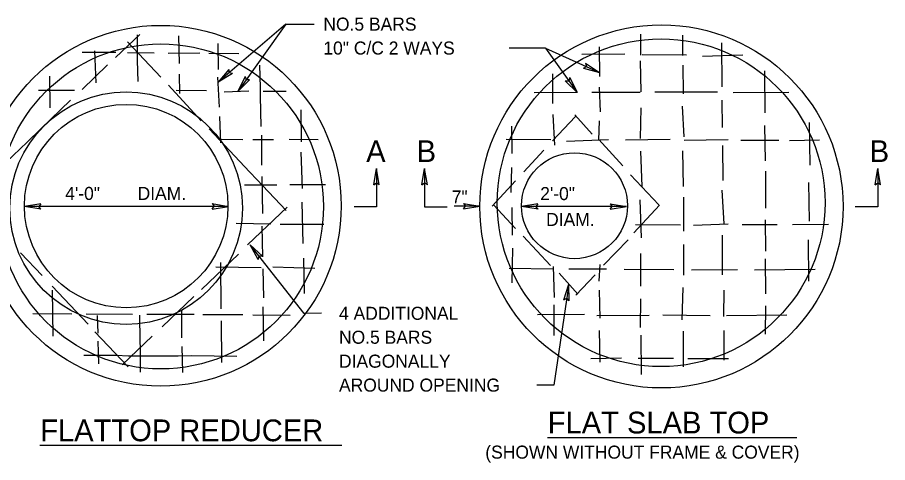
# Model space of a CAD drawing. Extents: x 1.8 to 9.1, y -6 to 4.
# Drawn here: x 5.032 to 9.029, y 1.931 to 3.977 of the extents above; entities that cross this region are included whole.
import ezdxf

# ---------------------------------------------------------------- set-up
doc = ezdxf.new("R2010")
doc.units = 0
for name, color, linetype in [('DETL-DIMS', 7, 'Continuous'), ('DETL-LINE', 7, 'Continuous'), ('DETL-NOTE', 7, 'Continuous'), ('DETL-TITL', 7, 'Continuous')]:
    doc.layers.add(name, color=color, linetype=linetype)

msp = doc.modelspace()

# ---------------------------------------------------------------- linework, layer by layer
at = {"layer": 'DETL-DIMS'}
for p, q in [((6.2643, 3.9457), (5.9535, 3.6792)), ((6.2643, 3.9457), (6.0444, 3.6358)), ((6.2643, 3.9457), (6.3953, 3.9457)), ((7.4577, 3.8358), (7.2901, 3.8358)), ((7.4577, 3.8358), (7.6027, 3.6313)), ((7.4577, 3.8358), (7.7054, 3.7231)), ((7.642, 3.7659), (7.7054, 3.7231)), ((7.642, 3.7659), (7.6454, 3.7505)), ((6.0027, 3.7379), (5.9535, 3.6792)), ((6.0191, 3.7187), (5.9535, 3.6792)), ((6.0027, 3.7379), (6.0037, 3.7222)), ((6.0191, 3.7187), (6.0037, 3.7222)), ((7.6316, 3.743), (7.6454, 3.7505)), ((7.6316, 3.743), (7.7054, 3.7231)), ((6.0779, 3.7046), (6.0444, 3.6358)), ((6.0984, 3.69), (6.0444, 3.6358)), ((6.0779, 3.7046), (6.0827, 3.6896)), ((6.0984, 3.69), (6.0827, 3.6896)), ((7.5488, 3.6856), (7.6027, 3.6313)), ((7.5488, 3.6856), (7.5645, 3.6851)), ((7.5693, 3.7001), (7.5645, 3.6851)), ((7.5693, 3.7001), (7.6027, 3.6313)), ((6.6686, 3.2069), (6.6809, 3.2824)), ((6.6937, 3.207), (6.6809, 3.2824)), ((6.8898, 3.207), (6.9026, 3.2824)), ((6.9149, 3.2069), (6.9026, 3.2824)), ((8.9716, 3.2069), (8.9839, 3.2824)), ((8.9967, 3.207), (8.9839, 3.2824)), ((6.6686, 3.2069), (6.6811, 3.2164)), ((6.6937, 3.207), (6.6811, 3.2164)), ((6.8898, 3.207), (6.9024, 3.2164)), ((6.9149, 3.2069), (6.9024, 3.2164)), ((8.9716, 3.2069), (8.9841, 3.2164)), ((8.9967, 3.207), (8.9841, 3.2164)), ((5.1396, 3.1206), (5.0641, 3.1084)), ((5.1396, 3.1206), (5.1301, 3.1081)), ((5.926, 3.1213), (6.0014, 3.1084)), ((5.926, 3.1213), (5.9354, 3.1086)), ((5.926, 3.1213), (6.0014, 3.1084)), ((5.926, 3.1213), (5.9354, 3.1086)), ((7.0804, 3.1216), (7.156, 3.1095)), ((7.0804, 3.1216), (7.0899, 3.1091)), ((7.4232, 3.1204), (7.3478, 3.1075)), ((7.4232, 3.1204), (7.4138, 3.1077)), ((7.7542, 3.1199), (7.8297, 3.1075)), ((7.7542, 3.1199), (7.7637, 3.1073)), ((5.1395, 3.0955), (5.0641, 3.1084)), ((6.0014, 3.1084), (5.0641, 3.1084)), ((5.1395, 3.0955), (5.1301, 3.1081)), ((5.9259, 3.0961), (5.9354, 3.1086)), ((5.9259, 3.0961), (5.9354, 3.1086)), ((5.9259, 3.0961), (6.0014, 3.1084)), ((5.9259, 3.0961), (6.0014, 3.1084)), ((7.156, 3.1095), (7.0381, 3.1095)), ((7.0806, 3.0964), (7.156, 3.1095)), ((7.0806, 3.0964), (7.0899, 3.1091)), ((7.4233, 3.0952), (7.3478, 3.1075)), ((7.8297, 3.1075), (7.3478, 3.1075)), ((7.4233, 3.0952), (7.4138, 3.1077)), ((7.7543, 3.0947), (7.8297, 3.1075)), ((7.7543, 3.0947), (7.7637, 3.1073)), ((6.3487, 2.6164), (6.1011, 2.9308)), ((6.1379, 2.8637), (6.1011, 2.9308)), ((6.1577, 2.8793), (6.1011, 2.9308)), ((6.1379, 2.8637), (6.142, 2.8789)), ((6.1577, 2.8793), (6.142, 2.8789)), ((7.5653, 2.7513), (7.4962, 2.2869)), ((7.5417, 2.6785), (7.5653, 2.7513)), ((7.5666, 2.6748), (7.5653, 2.7513)), ((7.5417, 2.6785), (7.5556, 2.686)), ((7.5666, 2.6748), (7.5556, 2.686)), ((6.4291, 2.6169), (6.3487, 2.6164)), ((7.4962, 2.2869), (7.4177, 2.2869))]:
    msp.add_line(p, q, dxfattribs=at)
for points in [[(6.6809, 3.2824), (6.6809, 3.1055), (6.578, 3.1055)], [(6.9026, 3.2824), (6.9026, 3.1055), (7.0056, 3.1055)], [(8.9839, 3.2824), (8.9839, 3.1055), (8.8809, 3.1055)]]:
    msp.add_lwpolyline(points, dxfattribs=at)
at = {"layer": 'DETL-LINE'}
for p, q in [((5.5938, 3.8977), (5.4829, 3.7919)), ((5.5835, 3.8021), (5.5834, 3.8972)), ((5.7724, 3.8922), (5.7755, 3.7655)), ((7.896, 3.8028), (7.8955, 3.9001)), ((8.0869, 3.8956), (8.0865, 3.8016)), ((5.6898, 3.7025), (5.5379, 3.8641)), ((5.9551, 3.7378), (5.9545, 3.8564)), ((7.704, 3.8406), (7.7057, 3.7052)), ((8.2701, 3.657), (8.2676, 3.86)), ((5.3286, 3.8172), (5.4838, 3.8168)), ((5.3862, 3.8229), (5.3914, 3.6755)), ((5.5379, 3.8147), (5.6592, 3.8137)), ((5.583, 3.7786), (5.5835, 3.8021)), ((5.7246, 3.8122), (5.8695, 3.8136)), ((5.9118, 3.8115), (6.0487, 3.8104)), ((7.6243, 3.8072), (7.8222, 3.8089)), ((7.9026, 3.8066), (8.1062, 3.8041)), ((8.1786, 3.7988), (8.3638, 3.8047)), ((5.4449, 3.759), (5.3294, 3.6449)), ((5.586, 3.6825), (5.583, 3.7786)), ((7.8965, 3.6349), (7.8943, 3.7774)), ((6.1436, 3.7569), (6.1462, 3.6547)), ((8.0886, 3.7565), (8.0902, 3.6253)), ((8.4639, 3.731), (8.4659, 3.5378)), ((5.1794, 3.7067), (5.1813, 3.5613)), ((5.7745, 3.7162), (5.7763, 3.6276)), ((5.9602, 3.5645), (5.9523, 3.7013)), ((7.4915, 3.5817), (7.4917, 3.7176)), ((5.2945, 3.6402), (5.1284, 3.6405)), ((5.8763, 3.5019), (5.726, 3.6653)), ((5.9005, 3.6393), (5.7603, 3.64)), ((6.1462, 3.6547), (6.1475, 3.6147)), ((7.7041, 3.6554), (7.7089, 3.5426)), ((6.0947, 3.6374), (5.9812, 3.6338)), ((6.1475, 3.6147), (6.1506, 3.4758)), ((6.2669, 3.6355), (6.161, 3.6358)), ((7.6012, 3.6313), (7.4057, 3.6305)), ((7.8932, 3.6316), (7.6699, 3.6322)), ((8.2477, 3.6329), (7.9595, 3.6325)), ((8.5759, 3.632), (8.3196, 3.63)), ((5.2758, 3.5967), (5.139, 3.4646)), ((7.8948, 3.4196), (7.8969, 3.5607)), ((8.0863, 3.5684), (8.0937, 3.4274)), ((8.2711, 3.4713), (8.269, 3.5968)), ((5.9656, 3.4006), (5.9614, 3.5217)), ((6.337, 3.4055), (6.3357, 3.5523)), ((7.4901, 3.4087), (7.5953, 3.5217)), ((7.501, 3.39), (7.4937, 3.53)), ((7.5924, 3.5292), (7.6723, 3.4408)), ((7.7049, 3.5007), (7.7007, 3.4123)), ((8.4643, 3.4795), (8.4666, 3.3168)), ((8.674, 3.2979), (8.6702, 3.4944)), ((5.139, 3.4646), (5.0769, 3.4035)), ((6.0987, 3.2651), (5.9121, 3.4648)), ((7.3012, 3.4771), (7.3037, 3.3506)), ((5.0769, 3.4035), (4.9456, 3.2815)), ((6.0678, 3.4136), (5.9554, 3.416)), ((6.2085, 3.4147), (6.113, 3.4142)), ((6.1524, 3.4352), (6.1527, 3.2978)), ((6.4127, 3.4134), (6.28, 3.4148)), ((7.277, 3.4168), (7.483, 3.4148)), ((7.5545, 3.4086), (7.7467, 3.4154)), ((7.7035, 3.4156), (7.8127, 3.295)), ((7.8253, 3.4135), (8.0307, 3.4172)), ((8.0946, 3.4128), (8.2963, 3.416)), ((8.3556, 3.4121), (8.53, 3.4127)), ((8.5794, 3.4102), (8.7171, 3.4138)), ((7.3587, 3.2673), (7.4508, 3.3671)), ((7.9012, 3.1992), (7.8951, 3.3622)), ((8.0874, 3.3639), (8.0906, 3.1994)), ((8.2734, 3.2273), (8.273, 3.3876)), ((6.341, 3.1898), (6.3352, 3.3576)), ((7.3017, 3.2867), (7.2981, 3.172)), ((6.1313, 3.2318), (6.0987, 3.2651)), ((6.1549, 3.245), (6.1573, 3.0761)), ((7.8478, 3.2534), (7.9783, 3.1155)), ((8.4687, 3.2694), (8.4682, 3.1006)), ((6.0754, 3.2077), (6.2231, 3.2067)), ((6.2665, 3.0888), (6.1313, 3.2318)), ((6.2838, 3.208), (6.4476, 3.2093)), ((7.212, 3.1094), (7.3199, 3.2252)), ((8.6712, 3.0403), (8.6679, 3.2175)), ((8.2791, 3.0285), (8.2694, 3.1826)), ((6.3439, 2.9375), (6.3405, 3.1278)), ((7.8982, 2.9641), (7.8926, 3.1389)), ((8.0914, 3.15), (8.0913, 2.9949)), ((6.0886, 2.931), (6.2709, 3.1051)), ((7.3202, 3.0066), (7.2185, 3.1156)), ((7.3037, 3.1038), (7.3048, 2.976)), ((7.982, 3.1141), (7.8633, 2.9869)), ((8.4662, 3.0461), (8.4684, 2.9017)), ((6.0374, 3.0303), (6.1959, 3.0275)), ((6.155, 3.0173), (6.1571, 2.8756)), ((6.2387, 3.0263), (6.4401, 3.027)), ((8.0775, 3.0225), (7.8715, 3.0232)), ((8.2975, 3.0267), (8.1377, 3.021)), ((8.5227, 3.0234), (8.3605, 3.0233)), ((8.7573, 3.0257), (8.5928, 3.0229)), ((7.48, 2.8369), (7.3551, 2.9716)), ((8.2715, 2.7934), (8.271, 2.9758)), ((7.8371, 2.9552), (7.7249, 2.8385)), ((8.0911, 2.9328), (8.0914, 2.7918)), ((8.668, 2.7652), (8.666, 2.9552)), ((5.0464, 2.8947), (5.145, 2.7906)), ((5.8775, 2.726), (6.0475, 2.8888)), ((7.3066, 2.9163), (7.3037, 2.7569)), ((7.8961, 2.7412), (7.8953, 2.8912)), ((5.9672, 2.6379), (5.9669, 2.8501)), ((6.3501, 2.7082), (6.3479, 2.8697)), ((7.7066, 2.8411), (7.7028, 2.765)), ((8.4671, 2.8679), (8.468, 2.7057)), ((6.1509, 2.8251), (5.9436, 2.8289)), ((6.1588, 2.8205), (6.1625, 2.6872)), ((6.3974, 2.8235), (6.2057, 2.8286)), ((7.2911, 2.824), (7.4909, 2.8206)), ((7.4991, 2.6894), (7.4951, 2.8319)), ((7.6067, 2.7042), (7.5211, 2.8015)), ((7.5652, 2.821), (7.7386, 2.8207)), ((7.8195, 2.8193), (8.0466, 2.8188)), ((8.1284, 2.8164), (8.3405, 2.8182)), ((8.418, 2.8159), (8.6959, 2.8195)), ((7.6866, 2.7935), (7.5973, 2.6999)), ((5.1909, 2.7239), (5.1949, 2.5125)), ((5.192, 2.7422), (5.3561, 2.5674)), ((7.7044, 2.7231), (7.707, 2.5939)), ((8.0889, 2.7358), (8.0845, 2.5868)), ((8.2763, 2.6025), (8.278, 2.7233)), ((5.6963, 2.5543), (5.8414, 2.6935)), ((7.8948, 2.5518), (7.896, 2.6834)), ((6.1596, 2.6469), (6.162, 2.4897)), ((7.4968, 2.5141), (7.4983, 2.6565)), ((8.4692, 2.6512), (8.4666, 2.5209)), ((5.2821, 2.6122), (5.1024, 2.6139)), ((5.5597, 2.6108), (5.3475, 2.6124)), ((5.3986, 2.6072), (5.4006, 2.5262)), ((5.595, 2.4909), (5.5939, 2.6081)), ((5.8444, 2.6121), (5.6255, 2.6116)), ((5.7848, 2.629), (5.7861, 2.5047)), ((6.0669, 2.61), (5.8839, 2.6105)), ((6.2846, 2.6063), (6.1129, 2.6087)), ((7.6363, 2.6118), (7.4205, 2.61)), ((7.934, 2.607), (7.6937, 2.606)), ((8.2146, 2.6059), (7.9974, 2.6078)), ((8.5668, 2.609), (8.2894, 2.6049)), ((5.9714, 2.3912), (5.9698, 2.5818)), ((5.3877, 2.5314), (5.5405, 2.3702)), ((7.704, 2.5384), (7.7067, 2.3922)), ((8.0895, 2.5342), (8.0909, 2.3715)), ((8.2787, 2.4018), (8.2785, 2.5376)), ((5.4006, 2.489), (5.4046, 2.3849)), ((5.5122, 2.3807), (5.6514, 2.5118)), ((5.5969, 2.4551), (5.595, 2.4909)), ((7.8992, 2.3355), (7.8969, 2.5165)), ((5.5974, 2.3459), (5.5969, 2.4551)), ((5.7869, 2.4637), (5.7903, 2.3445)), ((5.3364, 2.4238), (5.4857, 2.4246)), ((5.4857, 2.4246), (5.5425, 2.4219)), ((5.5425, 2.4219), (5.7707, 2.4215)), ((5.7707, 2.4215), (5.831, 2.4234)), ((5.831, 2.4234), (6.0398, 2.42)), ((7.6666, 2.4098), (7.8076, 2.4121)), ((7.8833, 2.4107), (8.0455, 2.4112)), ((8.1118, 2.4097), (8.298, 2.4085))]:
    msp.add_line(p, q, dxfattribs=at)
for centre, radius in [((5.69, 3.1109), 0.829), ((7.9903, 3.108), 0.8343), ((7.9888, 3.125), 0.753), ((5.6908, 3.108), 0.7469), ((5.531, 3.0998), 0.5342), ((5.5314, 3.1097), 0.4673), ((7.5911, 3.1112), 0.2433)]:
    msp.add_circle(centre, radius, dxfattribs=at)
at = {"layer": 'DETL-TITL'}
for p, q in [((7.4663, 2.046), (8.6118, 2.046)), ((5.135, 2.0103), (6.5217, 2.0103))]:
    msp.add_line(p, q, dxfattribs=at)

# ---------------------------------------------------------------- texts
at = {"layer": 'DETL-NOTE'}
for s, height, p in [('NO.5 BARS', 0.05998, (6.4372, 3.9157)), ('10" C/C 2 WAYS', 0.05998, (6.4372, 3.8058)), ('A', 0.1, (6.634, 3.3119)), ('B', 0.1, (6.8659, 3.3119)), ('B', 0.1, (8.9472, 3.3119)), ('4\'-0"', 0.05998, (5.2513, 3.1378)), ('DIAM.', 0.05998, (5.5839, 3.1378)), ('7"', 0.05998, (7.0269, 3.1215)), ('2\'-0"', 0.05998, (7.4335, 3.137)), ('DIAM.', 0.05998, (7.4605, 3.0181)), ('4 ADDITIONAL', 0.05998, (6.5091, 2.5869)), ('NO.5 BARS', 0.05998, (6.5091, 2.4769)), ('DIAGONALLY', 0.05998, (6.5091, 2.3669)), ('AROUND OPENING', 0.05998, (6.5091, 2.2569)), ('(SHOWN WITHOUT FRAME & COVER)', 0.05998, (7.1811, 1.9489))]:
    msp.add_text(s, height=height, dxfattribs=at).set_placement(p)
at = {"layer": 'DETL-TITL'}
for s, p in [('FLAT SLAB TOP', (7.4681, 2.0646)), ('FLATTOP REDUCER', (5.1365, 2.0289))]:
    msp.add_text(s, height=0.099994, dxfattribs=at).set_placement(p)

doc.saveas('drawing.dxf')
